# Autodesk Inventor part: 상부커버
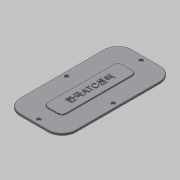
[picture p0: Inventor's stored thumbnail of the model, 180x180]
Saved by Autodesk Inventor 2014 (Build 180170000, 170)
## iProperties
Created: 2016-02
Part Number: 상부커버
Material: 일반
Document SubType Name: Modeling
Designer: mduedu
Density: 1 g/cm^3
Mass: 15.5198 g
Surface Area: 149.263 cm^2
Volume: 15.5198 cm^3
Appearance: 기본값
Author: mduedu
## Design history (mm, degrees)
sketch "스케치1"
  geometry: L1 (30, 60)-(-30, 60); L2 (-30, 60)-(-30, -60); L3 (-30, -60)-(30, -60); L4 (30, -60)-(30, 60); L5 (30, 60)-(-30, -60); L6 (-30, 60)-(30, -60); 1 further point
  constraints: 12 end point, 2 midpoint, 2 parallel, 1 horizontal, 1 perpendicular
  dimensions: "d0" = 60 distance of L2.end L3.end; "d2" = 120 distance of L1.end L2.end
extrude "돌출1" new body sketch "스케치1" distance "d3" = 2; taper "d4" = 0 deg
fillet "모깎기1" dims "d5" = 15
sketch "스케치2"
  geometry: L1 (30, 45)-(30, -45) reference; L2 (15, -60)-(-15, -60) reference; L3 (-30, -45)-(-30, 45) reference; L4 (-15, 60)-(15, 60) reference; L5 (25, 45)-(25, -45); L6 (15, -55)-(-15, -55); L7 (-25, -45)-(-25, 45); L8 (-15, 55)-(15, 55); A1 r 15 centre (15, 45) between (30, 45) and (15, 60) reference; A2 r 15 centre (15, -45) between (15, -60) and (30, -45) reference; A3 r 15 centre (-15, -45) between (-30, -45) and (-15, -60) reference; A4 r 15 centre (-15, 45) between (-15, 60) and (-30, 45) reference; A5 r 10 centre (15, 45) between (25, 45) and (15, 55); A6 r 10 centre (15, -45) between (15, -55) and (25, -45); A7 r 10 centre (-15, -45) between (-25, -45) and (-15, -55); A8 r 10 centre (-15, 45) between (-15, 55) and (-25, 45); 4 further points
  constraints: 8 end point, 8 point on circle, 4 centre point, 4 midpoint, 7 other
  dimensions: "d8" = 5 distance between parallel lines of L7 L3
hole "구멍1" sketch "스케치2" at (0, 55), (25, 0), (0, -55), (-25, 0) diameter "d9" = 4; stored, may be unused: countersink angle "d13" = 90 deg, drill point angle "d15" = 118 deg; dims "d10" = 6, "d11" = 4, "d12" = 2, "d14" = 8
sketch "스케치3"
  geometry: L1 (10, -40)-(-10, -40); L2 (-10, -40)-(-10, 40); L3 (-10, 40)-(10, 40); L4 (10, 40)-(10, -40); L5 (10, -40)-(-10, 40); L6 (-10, -40)-(10, 40); 1 further point
  constraints: 12 end point, 2 midpoint, 2 parallel, 1 horizontal, 1 perpendicular
  dimensions: "d16" = 80 distance of L1.end L2.end; "d18" = 20 distance of L2.end L3.end
extrude "돌출2" join sketch "스케치3" distance "d19" = 1; taper "d20" = 0 deg
fillet "모깎기2" dims "d21" = 5
fillet "모깎기3" dims "d22" = 0.3
fillet "모깎기4" dims "d23" = 0.3
sketch "스케치4"
  geometry: 2 further points
  constraints: 1 coincident, 1 other
feature "엠보싱1" sketch "스케치4" dims "d0" = 60, "d2" = 120, "d8" = 5, "d24" = 0.5, "d25" = 0
node "솔리드1"
node "절단 모서리 투영1"
